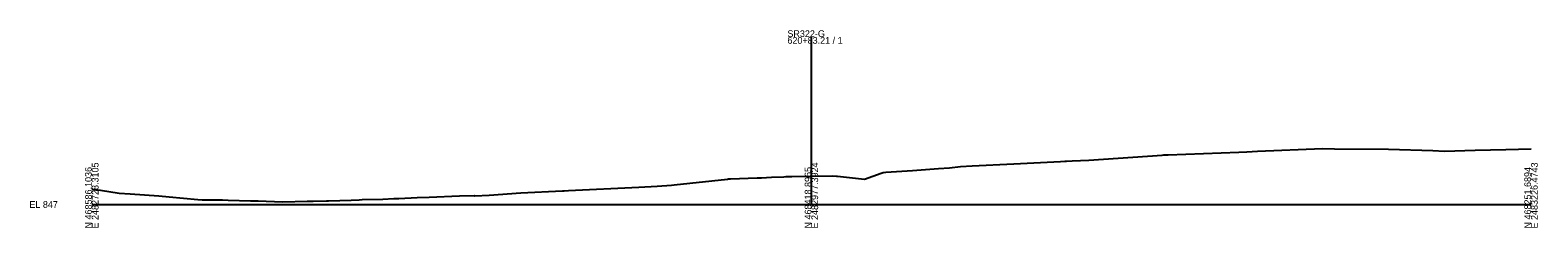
# Model space of a CAD drawing. Extents: x -26 to 4781, y -31 to 24738.
# Drawn here: x 3974 to 4603, y 21490 to 21572 of the extents above; entities that cross this region are included whole.
import ezdxf

# ---------------------------------------------------------------- set-up
doc = ezdxf.new("R2010")
doc.units = 0
doc.layers.add('DESIGN - SHEET - Light Grid', color=7, linetype='Continuous')
doc.layers.add('SURVEY - GROUND - Top of Ground', color=7, linetype='Continuous')

msp = doc.modelspace()

# ---------------------------------------------------------------- linework, layer by layer
at = {"layer": 'DESIGN - SHEET - Light Grid'}
for p, q in [((4300, 21500), (4300, 21569.65)), ((4000, 21500), (4300, 21500)), ((4300, 21500), (4600, 21500))]:
    msp.add_line(p, q, dxfattribs=at)
at = {"layer": 'SURVEY - GROUND - Top of Ground'}
msp.add_lwpolyline([(4000, 21506.35), (4001.72, 21506.14), (4003.61, 21505.95), (4011.41, 21504.7), (4016.02, 21504.42), (4028.01, 21503.6), (4032.28, 21503.22), (4044.23, 21502.14), (4046, 21501.97), (4046.58, 21501.98), (4054.45, 21501.91), (4056.83, 21501.83), (4066.1, 21501.56), (4069.41, 21501.49), (4072.66, 21501.33), (4079.66, 21501.06), (4089.85, 21501.31), (4090.61, 21501.33), (4092.34, 21501.36), (4097.85, 21501.45), (4098.64, 21501.47), (4108.08, 21501.83), (4111.53, 21501.98), (4112.71, 21502.04), (4121.36, 21502.27), (4125.92, 21502.44), (4128.02, 21502.51), (4135.66, 21502.85), (4140.69, 21503.05), (4153.3, 21503.6), (4159.36, 21503.8), (4159.7, 21503.63), (4165.6, 21503.87), (4178.8, 21504.89), (4196.29, 21505.65), (4196.89, 21505.68), (4198.71, 21505.77), (4227.99, 21507.23), (4235.63, 21507.64), (4241.61, 21508.02), (4242.85, 21508.11), (4265.01, 21510.57), (4265.44, 21510.62), (4266.28, 21510.66), (4277.39, 21511.07), (4279.21, 21511.15), (4283.32, 21511.37), (4288.57, 21511.51), (4289.52, 21511.64), (4291.78, 21511.66), (4300, 21511.75), (4308.81, 21511.85), (4310.4, 21511.84), (4310.87, 21511.76), (4322.07, 21510.51), (4329.04, 21513.05), (4329.86, 21513.31), (4330.96, 21513.42), (4342.2, 21514.15), (4353.05, 21514.91), (4357.5, 21515.29), (4362.14, 21515.82), (4367, 21516.13), (4384.38, 21516.84), (4403.82, 21517.92), (4405.58, 21518.05), (4406.31, 21518.07), (4408.65, 21518.16), (4415.63, 21518.41), (4446.28, 21520.56), (4446.87, 21520.59), (4448.66, 21520.67), (4478.13, 21521.79), (4481.54, 21521.93), (4485.9, 21522.12), (4513.01, 21523.22), (4518.02, 21523.1), (4540.63, 21522.94), (4559.06, 21522.47), (4563.94, 21522.21), (4576.67, 21522.63), (4589.45, 21522.88), (4600, 21523.09)], dxfattribs=at)

# ---------------------------------------------------------------- texts
at = {"layer": 'DESIGN - SHEET - Light Grid'}
for s, p in [('SR322-G', (4290, 21569.65)), ('620+83.21 / 1', (4290, 21566.85)), ('EL 847', (3974, 21498.6))]:
    msp.add_text(s, height=2.8, dxfattribs=at).set_placement(p)
for s, p in [('N 468586.1036', (4000, 21490)), ('E 2482728.3105', (4002.8, 21490)), ('N 468418.8965', (4300, 21490)), ('E 2482977.3924', (4302.8, 21490)), ('N 468251.6894', (4600, 21490)), ('E 2483226.4743', (4602.8, 21490))]:
    msp.add_text(s, height=2.8, rotation=90, dxfattribs=at).set_placement(p)

doc.saveas('drawing.dxf')
